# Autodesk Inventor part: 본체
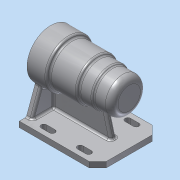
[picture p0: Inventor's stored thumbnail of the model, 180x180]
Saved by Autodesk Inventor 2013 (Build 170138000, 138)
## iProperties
Created: 2017-09
Part Number: 본체
Material: 알루미늄 6061
Document SubType Name: Modeling
Designer: Administrator
Density: 2.71036 g/cm^3
Mass: 697 g
Surface Area: 708.091 cm^2
Volume: 257.162 cm^3
Author: Administrator
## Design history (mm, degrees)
sketch "스케치2"
  geometry: L1 (0, 0)-(-112, 0); L2 (0, 0)-(0, 34); L3 (0, 34)-(-28, 34); L4 (-28, 34)-(-28, 30); L5 (-28, 30)-(-67, 30); L6 (-67, 30)-(-67, 27); L7 (-67, 27)-(-87, 27); L8 (-87, 27)-(-87, 25); L9 (-87, 25)-(-112, 25); L10 (-112, 25)-(-112, 0); L11 (0, 21)-(-15, 21); L12 (-15, 21)-(-15, 21); L13 (-18, 24)-(-66, 24); L14 (-69, 21)-(-69, 21); L15 (-69, 21)-(-80.7, 21); L16 (-81, 20.7)-(-81, 17.5); L17 (-81, 17.5)-(-98.7, 17.5); L18 (-99, 17.2)-(-99, 16); L19 (-99, 16)-(-102.7, 16); L20 (-103, 10.5)-(-103, 10.5); L21 (-106, 7.5)-(-106, 0); L22 (-103, 10.5)-(-103, 15.7); A1 r 0.3 centre (-102.7, 15.7) between (-102.7, 16) and (-103, 15.7); A2 r 0.3 centre (-98.7, 17.2) between (-98.7, 17.5) and (-99, 17.2); A3 r 0.3 centre (-80.7, 20.7) between (-80.7, 21) and (-81, 20.7); A4 r 3 centre (-18, 21) between (-15, 21) and (-18, 24); A5 r 3 centre (-66, 21) between (-66, 24) and (-69, 21); A6 r 3 centre (-103, 7.5) between (-103, 10.5) and (-106, 7.5); 6 further points
  constraints: 44 end point, 14 point on line, 12 parallel, 12 point on circle, 12 tangent, 8 perpendicular, 6 centre point, 4 equal radius, 1 collinear, 1 horizontal
  dimensions: "d1" = 68 diameter of L3 L1; "d3" = 60 diameter of L5 L1; "d4" = 54 diameter of L7 L1; "d5" = 50 diameter of L9 L1; "d6" = 25 distance of L8.end L9.end; "d7" = 112 distance of L1.start L1.end; "d8" = 45 distance between parallel lines of L10 L6; "d9" = 84 distance between parallel lines of L10 L4; "d10" = 15 distance of L11.start L11.end; "d11" = 54 distance of point (-15, 24) point (-69, 24); "d12" = 12 distance of L14.end point (-81, 21); "d13" = 18 distance of L16.end point (-99, 17.5); "d14" = 4 distance of L18.end point (-103, 16); "d15" = 3 distance of L20.start point (-106, 10.5); "d16" = 42 diameter of L11 L1; "d17" = 48 diameter of L13 L1; "d18" = 42 diameter of L15 L1; "d19" = 35 diameter of L17 L1; "d20" = 32 diameter of L19 L1; "d21" = 21 diameter of L20 L1; "d22" = 0.3 radius of A1; "d23" = 3 radius of A4
revolve "회전1" sketch "스케치2" stored, may be unused: angle "d24" = 90 deg
node "작업 평면1"
sketch "스케치3"
  geometry: L1 (0, 45)-(112, 45); L2 (112, 45)-(112, -45); L3 (112, -45)-(0, -45); L4 (0, -45)-(0, 45); 2 further points
  constraints: 8 end point, 2 parallel, 1 coincident, 1 horizontal, 1 midpoint, 1 perpendicular
  dimensions: "d26" = 90 distance of L3.end L1.start; "d28" = 112 distance of L1.start L1.end
extrude "돌출1" join sketch "스케치3" distance "d29" = 8; taper "d30" = 0 deg
sketch "스케치4"
  geometry: L1 (-70, -45)-(-70, 45) reference; L2 (-70, -45)-(-62, -45) reference; L3 (-62, 45)-(-62, -45) reference; L4 (-70, 45)-(-62, 45) reference; L5 (-26.008, -21.9)-(-62, -35); L6 (-26.008, 21.9)-(-62, 35); A1 r 34 centre (0, 0) between (-26.008, -21.9) and (-26.008, 21.9) reference
  constraints: 4 end point, 2 point on circle, 2 point on line
  dimensions: "d31" = 10 distance from line of L6.end L4; "d32" = 10 distance from line of L2 L5.end; "d33" = 110 deg angle of L3 L5; "d34" = 110 deg angle of L3 L6
extrude "돌출2" join sketch "스케치4" distance "d35" = 8; taper "d36" = 0 deg
sketch "스케치5"
  geometry: L1 (-87, -27)-(-67, -27) reference; L2 (0, -62)-(-112, -62) reference; L3 (-112, -25)-(-87, -25) reference; L4 (-90, -62)-(-80.622, -27); L5 (-112, -70)-(-112, -62) reference; 1 further point
  constraints: 2 end point, 2 point on line
  dimensions: "d37" = 22 distance from line of L5 L4.start; "d38" = 105 deg angle of L4 L2
feature "리브1" sketch "스케치5" dims "d39" = 1, "d40" = 8, "d41" = 0, "d42" = 0, "d43" = 1, "d44" = 1
chamfer "모따기1" distance "d45" = 12; stored, may be unused: second distance "d46" = 2, angle "d47" = 45 deg
sketch "스케치6"
  geometry: L1 (112, -33)-(112, 33) reference; L2 (76, 38)-(88, 38); L3 (76, 30)-(88, 30); L4 (24, 38)-(36, 38); L5 (36, 30)-(24, 30); A1 r 4 centre (88, 34) between (88, 38) and (88, 30); A2 r 4 centre (76, 34) between (76, 38) and (76, 30); A3 r 4 centre (36, 34) between (36, 38) and (36, 30); A4 r 4 centre (24, 34) between (24, 38) and (24, 30); 1 further point
  constraints: 8 end point, 8 point on circle, 7 tangent, 4 centre point, 3 horizontal alignment, 1 parallel
  dimensions: "d48" = 34 vertical distance of A2.centre point (0, 0); "d49" = 8 diameter of A1; "d50" = 8 diameter of A2; "d51" = 12 distance of A1.centre A2.centre; "d52" = 24 distance from line of L1 A1.centre; "d53" = 8 diameter of A4; "d54" = 8 diameter of A3; "d55" = 40 distance of A2.centre A3.centre; "d56" = 12 distance of A4.centre A3.centre
extrude "돌출3" cut sketch "스케치6" distance "d57" = 8; taper "d58" = 0 deg
fillet "모깎기1" dims "d62" = 3
fillet "모깎기2" dims "d63" = 3
fillet "모깎기3" dims "d64" = 3
fillet "모깎기4" dims "d65" = 3
chamfer "모따기2" distance "d66" = 1; stored, may be unused: second distance "d67" = 2, angle "d68" = 45 deg
node "작업 평면2"
sketch "스케치7"
  geometry: L1 (-19.971, 2.402)-(18.971, 2.402); L2 (18.971, 2.402)-(18.971, -2.402); L3 (18.971, -2.402)-(-19.971, -2.402); L4 (-19.971, -2.402)-(-19.971, 2.402); L5 (-19.971, 0)-(18.971, 0); L6 (-0.5, -2.402)-(-0.5, 2.402); L7 (47.5, -22)-(47.5, 22) reference; 2 further points
  constraints: 5 midpoint, 4 end point, 1 horizontal alignment, 2 other
  dimensions: "d69" = 48 distance between parallel lines of L7 L6
feature "엠보싱1" sketch "스케치7" dims "d19" = 35, "d70" = 0.5, "d71" = 0
fillet "모깎기5" dims "d72" = 9
sketch "스케치8" dims "d73" = 52
  geometry: C1 r 22 at (70, 45) reference; C2 r 2.516 at (96, 45); A1 r 34 centre (70, 45) between (45.289, 21.647) and (45.289, 68.353) reference; 1 further point
  constraints: 2 horizontal alignment, 1 centre point, 1 coincident, 2 other
hole "구멍1" sketch "스케치8" at (96, 45) diameter "d75" = 3.242; stored, may be unused: countersink angle "d79" = 90 deg, drill point angle "d81" = 118 deg; dims "d76" = 8, "d77" = 4, "d78" = 2, "d80" = 11
node "솔리드1"
pattern_linear "직사각형 패턴1" dims "d61" = 68
pattern_circular "원형 패턴1" dims angle "d83" = 360 deg
node "투영된 루프1"
